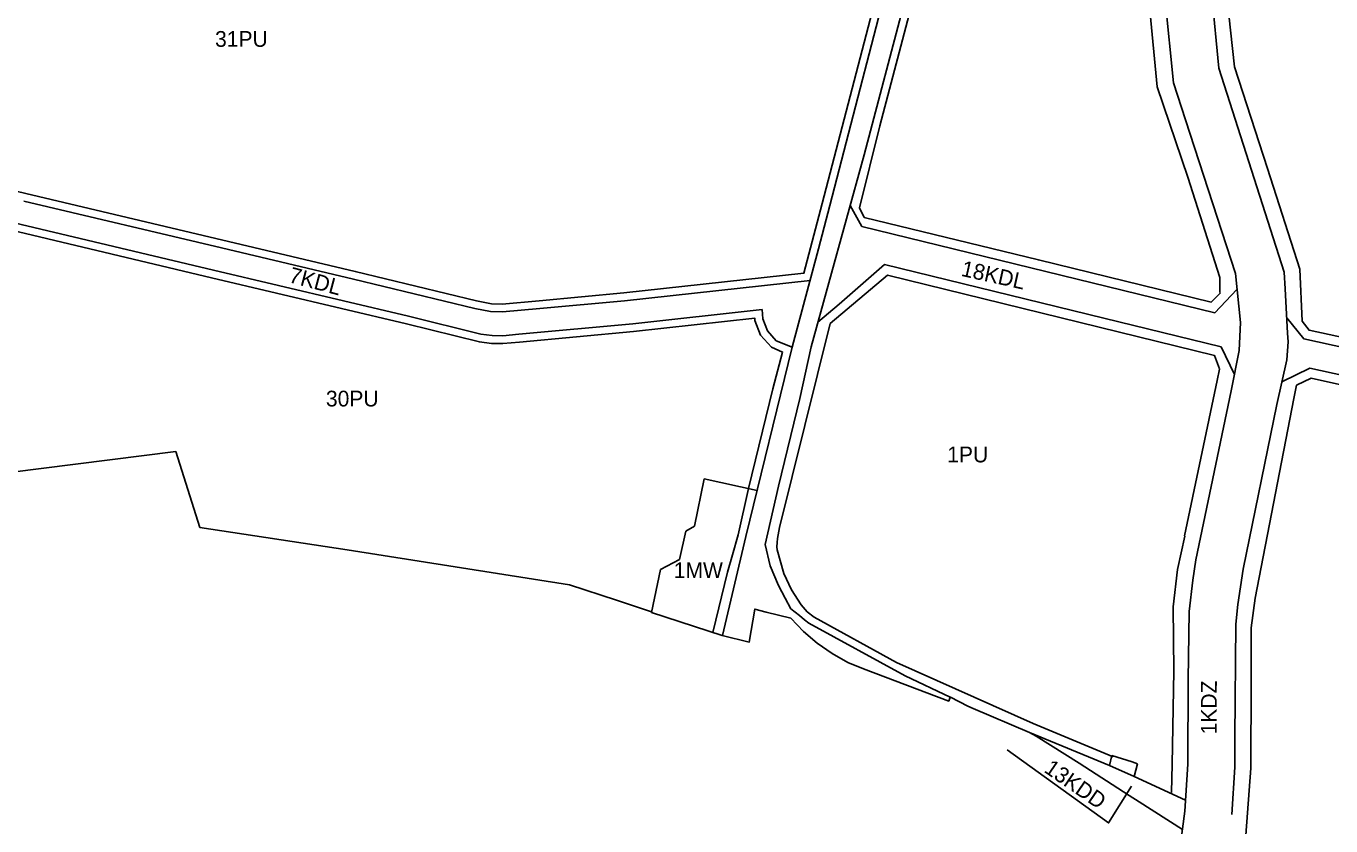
# Model space of a CAD drawing. Extents: x 7428203 to 7432868, y 5542672 to 5545406.
# Drawn here: x 7430591 to 7431420, y 5543351 to 5543859 of the extents above; entities that cross this region are included whole.
import ezdxf

# ---------------------------------------------------------------- set-up
doc = ezdxf.new("R2010")
doc.units = 0
for name, color, linetype in [('_GRANICA_MIASTA', 7, 'Continuous'), ('granicaBulwary', 7, 'Continuous'), ('MPZP_uchwalone_nieobowiazujace jeszcze_SZRAF', 7, 'Continuous')]:
    doc.layers.add(name, color=color, linetype=linetype)

msp = doc.modelspace()

# ---------------------------------------------------------------- linework, layer by layer
at = {"layer": '_GRANICA_MIASTA'}
for p, q in [((7431165.55, 5543937.59), (7431123.36, 5543776.97)), ((7431123.36, 5543776.97), (7431089.64, 5543655.03)), ((7430715.18, 5543717.91), (7430589.68, 5543747.58)), ((7431121.78, 5543731.38), (7431114.43, 5543744.68)), ((7430710.02, 5543703.71), (7430583.41, 5543733.76)), ((7430798.9, 5543698.1), (7430715.18, 5543717.91)), ((7431094.31, 5543717.17), (7431077.61, 5543654.85)), ((7430833.88, 5543674.42), (7430710.02, 5543703.71)), ((7431107.52, 5543682.17), (7431136.12, 5543707.23)), ((7431136.12, 5543707.23), (7431275.47, 5543673.31)), ((7430876.12, 5543679.31), (7430798.9, 5543698.1)), ((7431088.94, 5543697.11), (7430971.13, 5543684.26)), ((7430886.02, 5543677.47), (7430876.12, 5543679.31)), ((7430893.64, 5543677.18), (7430886.02, 5543677.47)), ((7430917.35, 5543679.36), (7430893.64, 5543677.18)), ((7430971.13, 5543684.26), (7430917.35, 5543679.36)), ((7431058.52, 5543678.7), (7430976.29, 5543669.73)), ((7431058.91, 5543672.88), (7431058.52, 5543678.7)), ((7431093.95, 5543670.63), (7431107.52, 5543682.17)), ((7430879.84, 5543663.13), (7430833.88, 5543674.42)), ((7430976.29, 5543669.73), (7430903.91, 5543663.06)), ((7431061.86, 5543665.19), (7431058.91, 5543672.88)), ((7430887.02, 5543662.23), (7430879.84, 5543663.13)), ((7430893.75, 5543662.12), (7430887.02, 5543662.23)), ((7430903.91, 5543663.06), (7430893.75, 5543662.12)), ((7431067.42, 5543658.94), (7431061.86, 5543665.19)), ((7431077.61, 5543654.85), (7431048.24, 5543534.65)), ((7431077.61, 5543654.85), (7431067.42, 5543658.94)), ((7431349.97, 5543655.13), (7431358.39, 5543637.39)), ((7430580.6, 5543575.31), (7430686.19, 5543588.57)), ((7430686.19, 5543588.57), (7430701.37, 5543540.45)), ((7431015.5, 5543541.29), (7431021.74, 5543571.34)), ((7431021.74, 5543571.34), (7431055.36, 5543563.79)), ((7430701.37, 5543540.45), (7430795.01, 5543526.17)), ((7431006.07, 5543520.07), (7431010.15, 5543537.97)), ((7431010.15, 5543537.97), (7431015.5, 5543541.29)), ((7431048.24, 5543534.65), (7431033.4, 5543471.78)), ((7430795.01, 5543526.17), (7430936.27, 5543503.99)), ((7430993.86, 5543513.61), (7431006.07, 5543520.07)), ((7431332, 5543506.96), (7431333.87, 5543519.93)), ((7430988.17, 5543486.46), (7430993.86, 5543513.61)), ((7430936.27, 5543503.99), (7430965.97, 5543494.23)), ((7431068.81, 5543503.5), (7431073.16, 5543495.48)), ((7431329.75, 5543486.99), (7431332, 5543506.96)), ((7431073.16, 5543495.48), (7431076.77, 5543488.83)), ((7430965.97, 5543494.23), (7430988.24, 5543486.82)), ((7431076.77, 5543488.83), (7431082.34, 5543484.54)), ((7431329.06, 5543443.63), (7431329.75, 5543486.99)), ((7430988.17, 5543486.46), (7431033.18, 5543471.84)), ((7431082.34, 5543484.54), (7431085.5, 5543481.75)), ((7431085.5, 5543481.75), (7431088.17, 5543479.66)), ((7431088.17, 5543479.66), (7431149.24, 5543446.28)), ((7431149.24, 5543446.28), (7431178, 5543432.69)), ((7431328.85, 5543390.18), (7431329.06, 5543443.63)), ((7431178, 5543432.69), (7431178.03, 5543432.68)), ((7431178.03, 5543432.68), (7431189.14, 5543427.07)), ((7431189.14, 5543427.07), (7431192.47, 5543425.38)), ((7431192.47, 5543425.38), (7431228.37, 5543410.35)), ((7431232.58, 5543407.99), (7431228.37, 5543410.35)), ((7431228.37, 5543410.35), (7431279.17, 5543389.27)), ((7431358.76, 5543407.05), (7431358.78, 5543388.18)), ((7431296.83, 5543390.4), (7431294.71, 5543382.36)), ((7431356.78, 5543358.24), (7431358.78, 5543388.18)), ((7431291.6, 5543370.34), (7431298.04, 5543366.23)), ((7431325.38, 5543348.66), (7431298.04, 5543366.23))]:
    msp.add_line(p, q, dxfattribs=at)
for points in [[(7431336.87, 5543994.72), (7431337.06, 5543957.82), (7431342.05, 5543907.45), (7431346.33, 5543901.64), (7431344.13, 5543878.23), (7431348.52, 5543831.97), (7431390, 5543702.36), (7431390.73, 5543691.85), (7431392.19, 5543663.75), (7431392.48, 5543658.26), (7431391.71, 5543646.79), (7431385.31, 5543618.42), (7431364, 5543513.86)], [(7431094.31, 5543717.17), (7431101.48, 5543744.76), (7431145.8, 5543915.56), (7431159, 5543967.17), (7431163.66, 5543988.83)], [(7431333.87, 5543519.93), (7431356.3, 5543627.18), (7431361.52, 5543652.65), (7431362.19, 5543670.59), (7431359.03, 5543701.57), (7431327.35, 5543799.07), (7431319.67, 5543822.68), (7431309.1, 5543927.71)], [(7431121.78, 5543731.38), (7431345.9, 5543676.71), (7431360.06, 5543691.52)], [(7431275.47, 5543673.31), (7431349.97, 5543655.13)], [(7431649.61, 5543661.01), (7431590.67, 5543649.59), (7431556.92, 5543645.08), (7431530.11, 5543643.19), (7431505.43, 5543642.9), (7431491.22, 5543643.07), (7431484.24, 5543643.38), (7431477.62, 5543644.1), (7431468.99, 5543645.49), (7431402.48, 5543660.21), (7431391.69, 5543673.42)], [(7431068.81, 5543503.5), (7431063.6, 5543515.96), (7431060.51, 5543529.56), (7431068.98, 5543566.54), (7431082.49, 5543622.16), (7431089.64, 5543655.03)], [(7431653.54, 5543644.48), (7431593.24, 5543632.39), (7431558.54, 5543627.75), (7431530.83, 5543625.8), (7431505.53, 5543625.5), (7431490.89, 5543625.68), (7431483.19, 5543626.02), (7431475.72, 5543626.83), (7431466.29, 5543628.35), (7431406.24, 5543641.45), (7431388.58, 5543632.9)], [(7431364, 5543513.86), (7431360.54, 5543491.54), (7431359.35, 5543479.02), (7431358.76, 5543407.05)], [(7431033.18, 5543471.84), (7431050.36, 5543467.64), (7431053.78, 5543488.54), (7431061.07, 5543486.69)], [(7431061.07, 5543486.69), (7431076.77, 5543482.72), (7431084.69, 5543474.3), (7431093.41, 5543466.95), (7431102.96, 5543460.38), (7431112.94, 5543454.78), (7431122.89, 5543450.59), (7431177.06, 5543430.2), (7431178, 5543432.69)], [(7431232.58, 5543407.99), (7431259.81, 5543390.73), (7431291.6, 5543370.34)], [(7431296.83, 5543390.4), (7431293.43, 5543391.53), (7431280.69, 5543395.65), (7431279.17, 5543389.27), (7431294.67, 5543382.38)], [(7431324.03, 5543337.93), (7431326.85, 5543360.24), (7431328.85, 5543390.18)], [(7431327.32, 5543367.4), (7431294.67, 5543382.38)]]:
    msp.add_lwpolyline(points, dxfattribs=at)
at = {"layer": 'granicaBulwary'}
msp.add_lwpolyline([(7431214.03, 5543399.28), (7431278.49, 5543352.81), (7431293.17, 5543376.18)], dxfattribs=at)
at = {"layer": 'MPZP_uchwalone_nieobowiazujace jeszcze_SZRAF'}
for p, q in [((7431161.79, 5543903.59), (7431133.34, 5543795.27)), ((7431133.34, 5543795.27), (7431120.27, 5543743.3)), ((7431120.26, 5543743.37), (7431123.21, 5543737.21)), ((7431101.77, 5543669.93), (7431069.64, 5543540.37)), ((7431407.18, 5543635.16), (7431397.88, 5543630.74)), ((7431447.06, 5543626.25), (7431407.18, 5543635.16)), ((7431069.64, 5543540.37), (7431068.32, 5543533.48)), ((7431068, 5543530.75), (7431067.87, 5543528.16)), ((7431067.87, 5543528.16), (7431068.02, 5543526.15)), ((7431068.32, 5543533.48), (7431068, 5543530.75)), ((7431068.02, 5543526.15), (7431072.2, 5543511.28)), ((7431072.2, 5543511.28), (7431077.25, 5543500.75)), ((7431077.25, 5543500.75), (7431083.31, 5543491.36)), ((7431083.31, 5543491.36), (7431087.01, 5543486.91)), ((7431087.01, 5543486.91), (7431091.6, 5543483.47)), ((7431091.6, 5543483.47), (7431143.91, 5543454.73)), ((7431143.91, 5543454.73), (7431230.67, 5543415.89)), ((7431230.67, 5543415.89), (7431281.47, 5543394.81))]:
    msp.add_line(p, q, dxfattribs=at)
for points in [[(7431349.2, 5543689.58), (7431349.15, 5543699.08), (7431349.15, 5543699.08), (7431328.95, 5543762.85), (7431309.36, 5543820.12), (7431299.15, 5543926.71), (7431295.65, 5543954.49), (7431295.22, 5543975.54), (7431296.68, 5544010.53), (7431304.12, 5544109.78), (7431310.11, 5544189.63), (7431300.19, 5544190.78)], [(7430364.22, 5543909.88), (7430366.87, 5543843.51), (7430367.55, 5543835.53), (7430369.32, 5543828.42), (7430372.62, 5543820.8), (7430376.79, 5543814.37), (7430380.91, 5543809.7), (7430385.37, 5543805.8), (7430393.16, 5543800.91), (7430401.08, 5543798.21), (7430590.92, 5543752.42), (7430800.06, 5543702.97), (7430877.17, 5543684.2), (7430886.57, 5543682.45), (7430893.51, 5543682.18), (7430916.89, 5543684.34), (7430970.59, 5543689.23), (7431085, 5543701.71), (7431096.64, 5543746.01), (7431141.07, 5543916.56)], [(7431356.33, 5543901.17), (7431353.52, 5543877.68), (7431358.38, 5543832.7), (7431379.41, 5543768.24), (7431399.89, 5543704.26), (7431401.46, 5543671.4)], [(7431065.36, 5543628.41), (7431071.52, 5543651.7), (7431064.4, 5543654.82), (7431057.52, 5543662.55), (7431053.97, 5543671.8), (7431053.88, 5543673.17), (7430976.83, 5543664.76), (7430904.37, 5543658.08), (7430893.94, 5543657.12), (7430886.66, 5543657.24), (7430878.99, 5543658.2), (7430832.69, 5543669.56), (7430708.87, 5543698.85), (7430499.81, 5543748.5), (7430424.28, 5543766.84), (7430394.08, 5543774.18), (7430383.18, 5543777.9), (7430377.88, 5543780.73), (7430363.42, 5543791.79), (7430360.03, 5543794.93), (7430352.73, 5543805.17)], [(7431123.21, 5543737.21), (7431233.95, 5543710.19), (7431343.72, 5543683.42), (7431349.51, 5543689.34)], [(7431348.94, 5543641.03), (7431345.78, 5543649.62), (7431138.11, 5543700.58), (7431101.77, 5543669.93)], [(7431401.46, 5543671.4), (7431405.81, 5543665.62), (7431474.26, 5543650.72), (7431488.04, 5543649.22), (7431505.94, 5543648.91), (7431543.09, 5543650.12), (7431556.31, 5543651.05), (7431591.53, 5543655.87), (7431645.69, 5543666.48), (7431650.7, 5543673.62)], [(7431326.82, 5543535.01), (7431347.4, 5543633.65), (7431348.92, 5543640.96)], [(7431027.16, 5543473.79), (7431036.56, 5543512.04), (7431039.75, 5543523.06), (7431043.31, 5543535.8), (7431049.83, 5543565.15), (7431065.36, 5543628.41)], [(7431397.88, 5543630.74), (7431396.26, 5543622.17), (7431371.53, 5543495.49)], [(7431322.26, 5543513.71), (7431326.84, 5543534.92)], [(7431318.53, 5543372.2), (7431318.85, 5543390.22), (7431319.91, 5543449.08), (7431319.53, 5543490.11), (7431322.26, 5543513.71)], [(7431371.53, 5543495.49), (7431369.17, 5543476.66), (7431369.05, 5543442.73), (7431368.76, 5543387.51), (7431365.58, 5543344.99)]]:
    msp.add_lwpolyline(points, dxfattribs=at)

# ---------------------------------------------------------------- texts
at = {"layer": 'granicaBulwary'}
for s, p in [('31PU', (7430711.09, 5543845.49)), ('30PU', (7430781.49, 5543617.2)), ('1PU', (7431176.05, 5543581.73)), ('1MW', (7431002.38, 5543508.25))]:
    msp.add_text(s, height=10, dxfattribs=at).set_placement(p)
for s, rotation, p in [('7KDL', 345.09526, (7430757.37, 5543696.21)), ('18KDL', 347.50629, (7431184.37, 5543700.18)), ('1KDZ', 89.7666, (7431347.14, 5543409.02)), ('13KDD', 325.46153, (7431236.91, 5543385.55))]:
    msp.add_text(s, height=10, rotation=rotation, dxfattribs=at).set_placement(p)

doc.saveas('drawing.dxf')
